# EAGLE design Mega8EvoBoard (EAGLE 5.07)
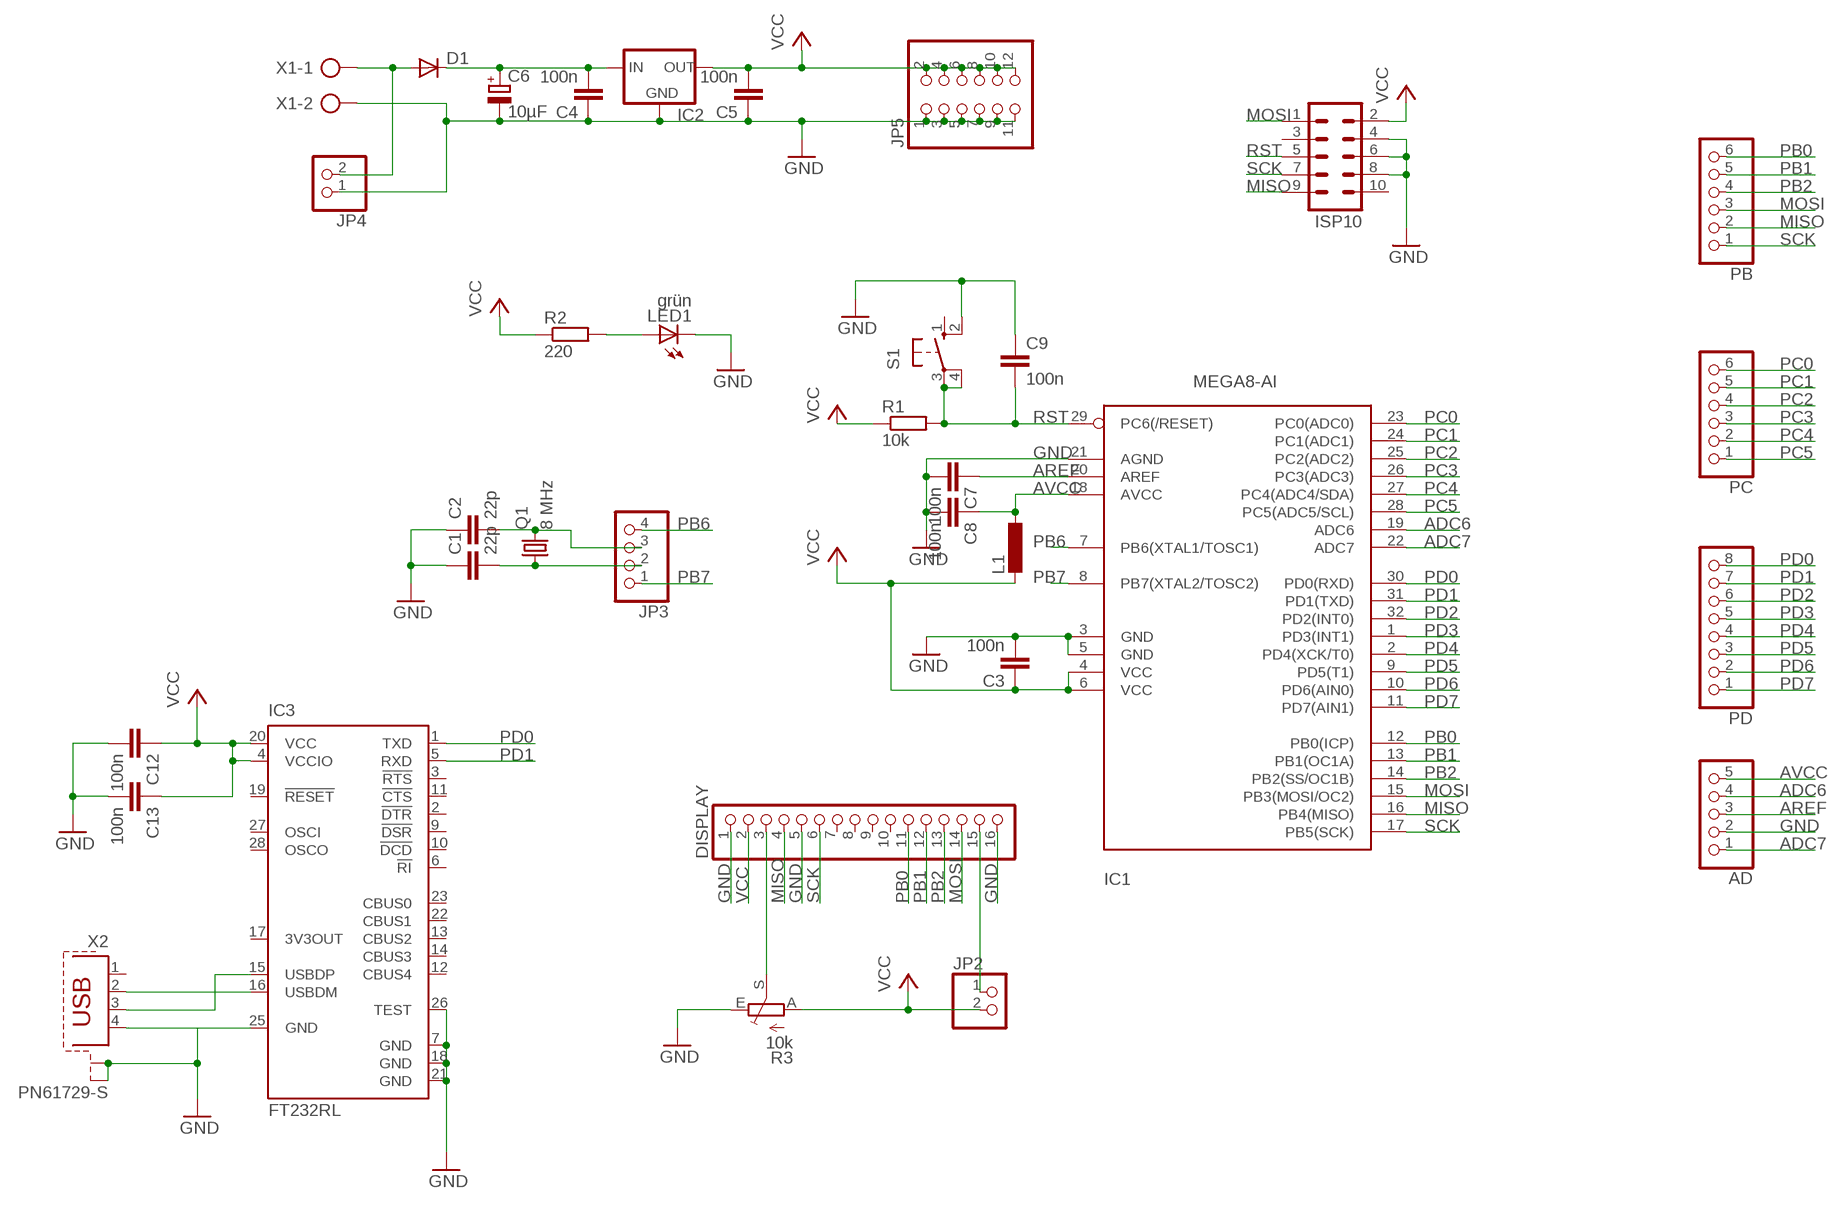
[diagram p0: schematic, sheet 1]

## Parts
AD  PINHD-1X5  [1X05]
C1  22p  C-EUC0805  [C0805]
C2  22p  C-EUC0805  [C0805]
C3  100n  C-EUC1206  [C1206]
C4  100n  C-EUC1206  [C1206]
C5  100n  C-EUC1206  [C1206]
C6  10µF  CPOL-EUE2.5-6  [E2,5-6]
C7  100n  C-EUC1206  [C1206]
C8  100n  C-EUC1206  [C1206]
C9  100n  C-EUC1206  [C1206]
C12  100n  C-EUC1206  [C1206]
C13  100n  C-EUC1206  [C1206]
D1  DIODE-MINIMELF  [MINIMELF]
DISPLAY  PINHD-1X16  [1X16]
IC1  MEGA8-AI  [TQFP32-08]
IC2  78XXS  [78XXS]
IC3  FT232RL  [SSOP28]
ISP10  ML10  [ML10]
JP2  PINHD-1X2  [1X02]
JP3  PINHD-1X4  [1X04]
JP4  PINHD-1X2  [1X02]
JP5  PINHD-2X6  [2X06]
L1  L-EUL2012C  [L2012C]
LED1  grün  LED3MM  [LED3MM]
PB  PINHD-1X6  [1X06]
PC  PINHD-1X6  [1X06]
PD  PINHD-1X8  [1X08]
Q1  8 MHz  CRYSTALHC49UP  [HC49UP]
R1  10k  R-EU_R0805  [R0805]
R2  220  R-EU_R0805  [R0805]
R3  10k  TRIM_EU-PT10  [PT-10]
S1  10-XX  [B3F-10XX]
X1  AK500/2  [AK500/2]
X2  PN61729-S  [PN61729-S]

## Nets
ADC6: AD.4 IC1.19(ADC6)
ADC7: AD.1 IC1.22(ADC7)
AREF: AD.3 C7.1 IC1.20(AREF)
AVCC: AD.5 C8.1 IC1.18(AVCC) L1.1
GND: AD.2 C1.1 C2.1 C3.2 C4.1 C5.1 C6.- C7.2 C8.2 C9.1 C12.2 C13.2 DISPLAY.1 DISPLAY.5 DISPLAY.16 IC1.3(GND) IC1.5(GND) IC1.21(AGND) IC2.GND IC3.7(GND) IC3.18(GND) IC3.21(GND) IC3.25(GND) IC3.26(TEST) ISP10.4 ISP10.6 ISP10.8 JP4.1 JP5.1 JP5.3 JP5.5 JP5.7 JP5.9 JP5.11 LED1.K(C) R3.E S1.2(S1) X1.2 X2.4 X2.S1 X2.S2
MISO: DISPLAY.4 IC1.16(PB4(MISO)) ISP10.9 PB.2
MOSI: DISPLAY.14 IC1.15(PB3(MOSI/OC2)) ISP10.1 PB.3
N$1: D1.A JP4.2 X1.1
N$2: LED1.A R2.2
N$3: C1.2 JP3.2 Q1.1
N$4: DISPLAY.15 JP2.1
N$5: DISPLAY.3 R3.S
N$9: C4.2 C6.+ D1.C IC2.IN
N$12: IC3.16(USBDM) X2.2
N$13: IC3.15(USBDP) X2.3
N$32: C2.2 JP3.3 Q1.2
PB0: DISPLAY.11 IC1.12(PB0(ICP)) PB.6
PB1: DISPLAY.12 IC1.13(PB1(OC1A)) PB.5
PB2: DISPLAY.13 IC1.14(PB2(SS/OC1B)) PB.4
PB6: IC1.7(PB6(XTAL1/TOSC1)) JP3.4
PB7: IC1.8(PB7(XTAL2/TOSC2)) JP3.1
PC0: IC1.23(PC0(ADC0)) PC.6
PC1: IC1.24(PC1(ADC1)) PC.5
PC2: IC1.25(PC2(ADC2)) PC.4
PC3: IC1.26(PC3(ADC3)) PC.3
PC4: IC1.27(PC4(ADC4/SDA)) PC.2
PC5: IC1.28(PC5(ADC5/SCL)) PC.1
PD0: IC1.30(PD0(RXD)) IC3.1(TXD) PD.8
PD1: IC1.31(PD1(TXD)) IC3.5(RXD) PD.7
PD2: IC1.32(PD2(INT0)) PD.6
PD3: IC1.1(PD3(INT1)) PD.5
PD4: IC1.2(PD4(XCK/T0)) PD.4
PD5: IC1.9(PD5(T1)) PD.3
PD6: IC1.10(PD6(AIN0)) PD.2
PD7: IC1.11(PD7(AIN1)) PD.1
RST: C9.2 IC1.29(PC6(/RESET)) ISP10.5 R1.2 S1.3(P) S1.4(P1)
SCK: DISPLAY.6 IC1.17(PB5(SCK)) ISP10.7 PB.1
VCC: C3.1 C5.2 C12.1 C13.1 DISPLAY.2 IC1.4(VCC) IC1.6(VCC) IC2.OUT IC3.4(VCCIO) IC3.20(VCC) ISP10.2 JP2.2 JP5.2 JP5.4 JP5.6 JP5.8 JP5.10 JP5.12 L1.2 R1.1 R2.1 R3.A
Unconnected: DISPLAY.7 DISPLAY.8 DISPLAY.9 DISPLAY.10 IC3.2(!DTR) IC3.3(!RTS) IC3.6(!RI) IC3.9(!DSR) IC3.10(!DCD) IC3.11(!CTS) IC3.12(CBUS4) IC3.13(CBUS2) IC3.14(CBUS3) IC3.17(3V3OUT) IC3.19(!RESET) IC3.22(CBUS1) IC3.23(CBUS0) IC3.27(OSCI) IC3.28(OSCO) ISP10.3 ISP10.10 S1.1(S) X2.1

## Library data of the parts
AD = pinhead:PINHD-1X5: PIN HEADER
C1-C5 C7-C9 C12 C13 = rcl:C-EU: CAPACITOR, European symbol
C6 = rcl:CPOL-EU: POLARIZED CAPACITOR, European symbol
D1 = diode:DIODE-: DIODE
DISPLAY = pinhead:PINHD-1X16: PIN HEADER
IC1 = atmel:MEGA8: MICROCONTROLLER 8 Kbytes FLASH 1 kbytes SRAM 512 bytes EEPROM USART 6-channel 10 bit ADC 2-channel 8 bit ADC Source: avr.lbr
IC2 = v-reg:78XXS: VOLTAGE REGULATOR
IC3 = ftdichip:FT232R: Source: http://www.ftdichip.com/Documents/DataSheets/DS_FT232R_v104.pdf
ISP10 = con-harting-ml:ML10: HARTING
JP2 JP4 = pinhead:PINHD-1X2: PIN HEADER
JP3 = pinhead:PINHD-1X4: PIN HEADER
JP5 = pinhead:PINHD-2X6: PIN HEADER
L1 = rcl:L-EU: INDUCTOR, European symbol
LED1 = led:LED: LED
PB PC = pinhead:PINHD-1X6: PIN HEADER
PD = pinhead:PINHD-1X8: PIN HEADER
Q1 = crystal:CRYSTAL: CRYSTAL
R1 R2 = rcl:R-EU_: RESISTOR, European symbol
R3 = pot:TRIM_EU-: POTENTIOMETER
S1 = switch-omron:10-XX: OMRON SWITCH
X1 = con-ptr500:AK500/2: CONNECTOR
X2 = con-berg:PN61729-S: BERG USB connector

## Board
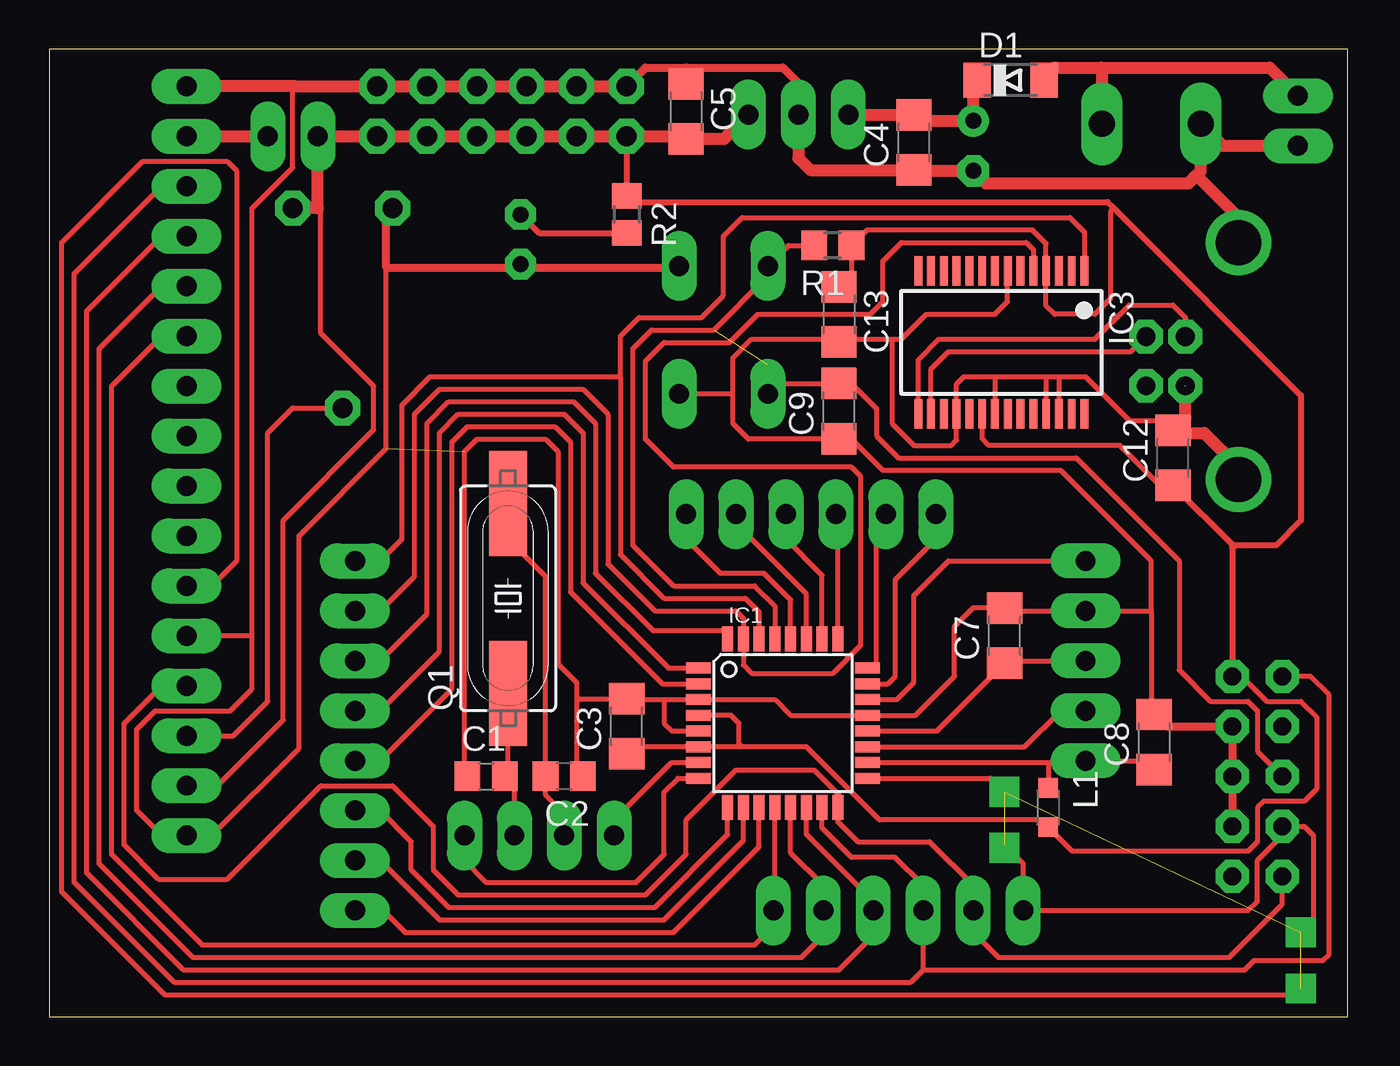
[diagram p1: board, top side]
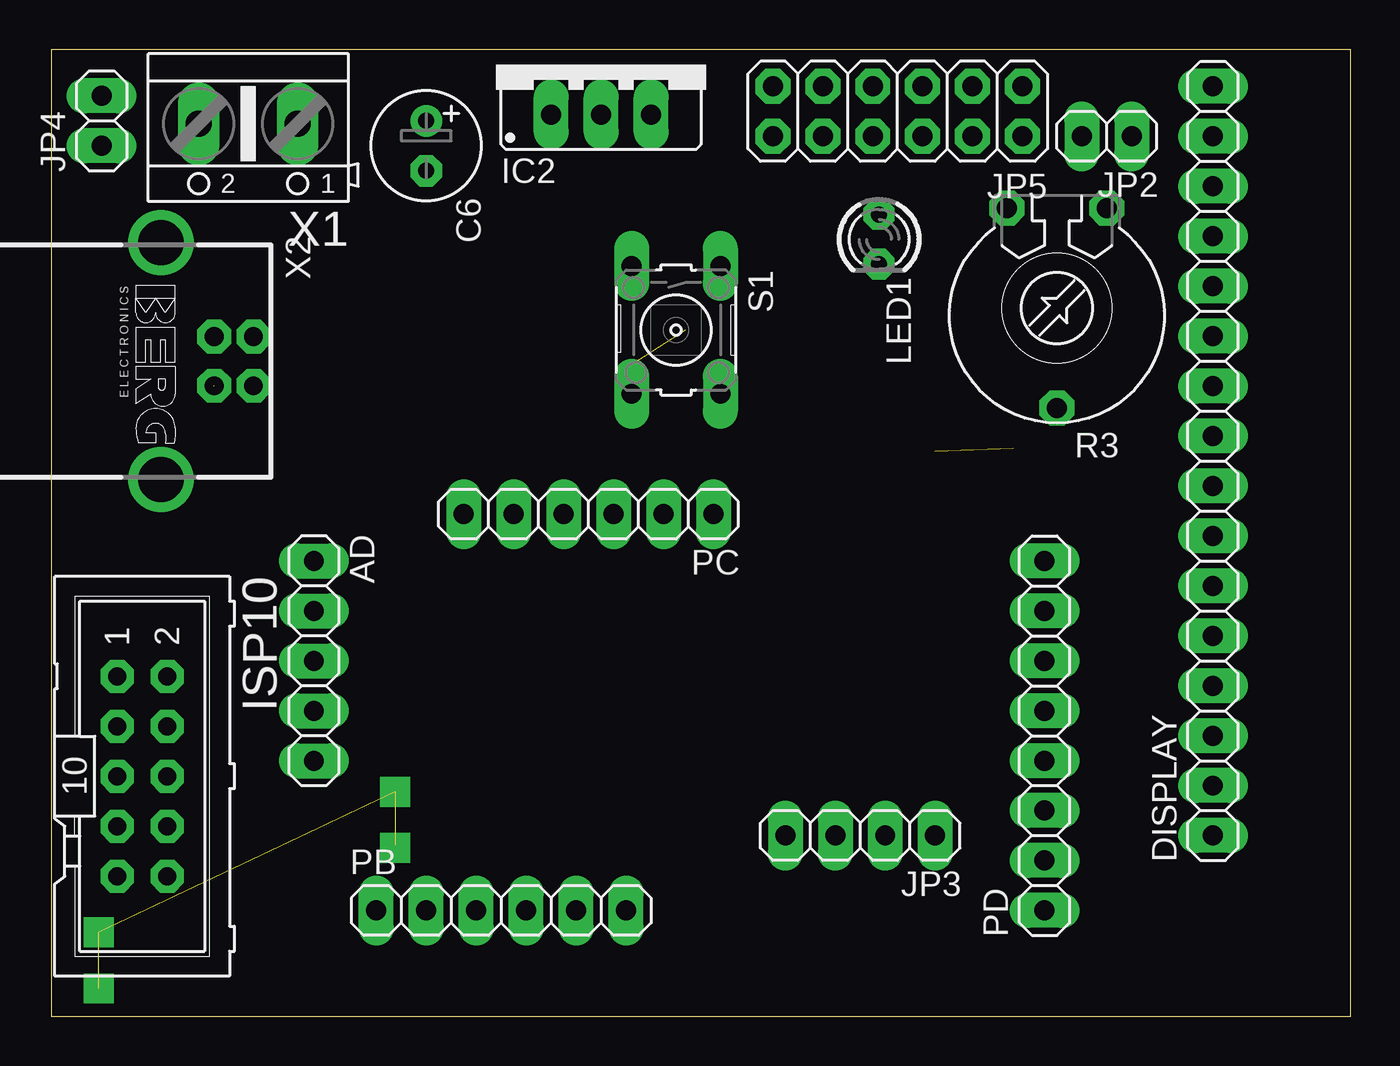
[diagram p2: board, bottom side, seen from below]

Size 66.03 x 49.2 mm. Coordinates in mm from the lower left corner, seen from the top.
Outline: 0,0 66.03,0 66.03,49.2 0,49.2 0,0
Copper layers (1*16): Top 0.035mm / dielectric 1.5mm / Bottom 0.035mm
Design rules "default *": minimum track width 10mil, minimum drill 24mil, track to track 8mil, track to pad 8mil, pad to pad 8mil, via to via 8mil, smd to smd 8mil, copper to edge 40mil, drill to drill 8mil, minimum pad ring 15mil, minimum via ring 8mil, stop-mask expansion 4mil, vias tented up to drill 0mil, thermal gap 10mil

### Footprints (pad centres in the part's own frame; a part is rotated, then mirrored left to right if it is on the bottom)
1X05 = drill 1.016 long: 1 -5.08,0; 2 -2.54,0; 3 0,0; 4 2.54,0; 5 5.08,0
C0805 = smd 1.3 x 1.5: 1 -0.95,0; 2 0.95,0
C1206 = smd 1.6 x 1.8: 1 -1.4,0; 2 1.4,0
E2,5-6 = drill 0.813 pad 1.6 round: + -1.27,0 | drill 0.813 pad 1.6 octagon: - 1.27,0
MINIMELF = smd 1.4 x 1.8: A 1.7,0; C -1.7,0
1X16 = drill 1.016 long: 1 -19.05,0; 2 -16.51,0; 3 -13.97,0; 4 -11.43,0; 5 -8.89,0; 6 -6.35,0; 7 -3.81,0; 8 -1.27,0; 9 1.27,0; 10 3.81,0; 11 6.35,0; 12 8.89,0; 13 11.43,0; 14 13.97,0; 15 16.51,0; 16 19.05,0
TQFP32-08 = smd 1.27 x 0.559: 1 -4.293,2.8; 2 -4.293,2; 3 -4.293,1.2; 4 -4.293,0.4; 5 -4.293,-0.4; 6 -4.293,-1.2; 7 -4.293,-2; 8 -4.293,-2.8; 17 4.293,-2.8; 18 4.293,-2; 19 4.293,-1.2; 20 4.293,-0.4; 21 4.293,0.4; 22 4.293,1.2; 23 4.293,2; 24 4.293,2.8 | smd 0.559 x 1.27: 9 -2.8,-4.293; 10 -2,-4.293; 11 -1.2,-4.293; 12 -0.4,-4.293; 13 0.4,-4.293; 14 1.2,-4.293; 15 2,-4.293; 16 2.8,-4.293; 25 2.8,4.293; 26 2,4.293; 27 1.2,4.293; 28 0.4,4.293; 29 -0.4,4.293; 30 -1.2,4.293; 31 -2,4.293; 32 -2.8,4.293
78XXS = drill 1.016 long: GND 0,-2.54; IN -2.54,-2.54; OUT 2.54,-2.54
SSOP28 = smd 0.4 x 1.5: 1 -4.225,-3.625; 2 -3.575,-3.625; 3 -2.925,-3.625; 4 -2.275,-3.625; 5 -1.625,-3.625; 6 -0.975,-3.625; 7 -0.325,-3.625; 8 0.325,-3.625; 9 0.975,-3.625; 10 1.625,-3.625; 11 2.275,-3.625; 12 2.925,-3.625; 13 3.575,-3.625; 14 4.225,-3.625; 15 4.225,3.625; 16 3.575,3.625; 17 2.925,3.625; 18 2.275,3.625; 19 1.625,3.625; 20 0.975,3.625; 21 0.325,3.625; 22 -0.325,3.625; 23 -0.975,3.625; 24 -1.625,3.625; 25 -2.275,3.625; 26 -2.925,3.625; 27 -3.575,3.625; 28 -4.225,3.625
ML10 = drill 0.914 octagon: 1 -5.08,-1.27; 2 -5.08,1.27; 3 -2.54,-1.27; 4 -2.54,1.27; 5 0,-1.27; 6 0,1.27; 7 2.54,-1.27; 8 2.54,1.27; 9 5.08,-1.27; 10 5.08,1.27
1X02 = drill 1.016 long: 1 -1.27,0; 2 1.27,0
1X04 = drill 1.016 long: 1 -3.81,0; 2 -1.27,0; 3 1.27,0; 4 3.81,0
2X06 = drill 1.016 octagon: 1 -6.35,-1.27; 2 -6.35,1.27; 3 -3.81,-1.27; 4 -3.81,1.27; 5 -1.27,-1.27; 6 -1.27,1.27; 7 1.27,-1.27; 8 1.27,1.27; 9 3.81,-1.27; 10 3.81,1.27; 11 6.35,-1.27; 12 6.35,1.27
L2012C = smd 1 x 1: 1 -1,0; 2 1,0
LED3MM = drill 0.813 octagon: A -1.27,0; K 1.27,0
1X06 = drill 1.016 long: 1 -6.35,0; 2 -3.81,0; 3 -1.27,0; 4 1.27,0; 5 3.81,0; 6 6.35,0
1X08 = drill 1.016 long: 1 -8.89,0; 2 -6.35,0; 3 -3.81,0; 4 -1.27,0; 5 1.27,0; 6 3.81,0; 7 6.35,0; 8 8.89,0
HC49UP = smd 5.334 x 1.93: 1 -4.826,0; 2 4.826,0
R0805 = smd 1.3 x 1.5: 1 -0.95,0; 2 0.95,0
PT-10 = drill 1.016 octagon: A -2.54,-5.08; E 2.54,-5.08; S 0,5.08
B3F-10XX = drill 1.016 long: 1 -3.251,2.261; 2 3.251,2.261; 3 -3.251,-2.261; 4 3.251,-2.261
AK500/2 = drill 1.321 long: 1 -2.515,0; 2 2.515,0
PN61729-S = drill 0.95 octagon: 1 1.25,4.71; 2 -1.25,4.71; 3 -1.25,2.71; 4 1.25,2.71 | drill 2.3 pad 2.9 round: S1 -6.02,0; S2 6.02,0

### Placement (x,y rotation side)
AD  52.7,18.1 270 bottom
C1  22.22,12.22 0 top
C2  26.19,12.22 180 top
C3  29.37,14.76 90 top
C4  43.97,44.45 90 top
C5  32.38,46.04 270 top
C6  46.99,44.29 270 bottom
C7  48.58,19.37 90 top
C8  56.2,13.97 90 top
C9  40.16,30.8 90 top
C12  57.15,28.42 90 top
C13  40.16,35.72 270 top
D1  48.9,47.62 0 top
DISPLAY  6.99,28.26 90 bottom
IC1  37.31,14.92 0 top
IC2  38.1,48.42 0 bottom
IC3  48.42,34.29 180 top
ISP10  61.44,12.22 270 bottom
JP2  12.38,44.77 180 bottom
JP3  24.92,9.21 180 bottom
JP4  63.5,45.56 90 bottom
JP5  23.02,46.04 180 bottom
L1  50.8,10.64 270 top
LED1  23.97,39.53 270 bottom
PB  43.18,5.4 0 bottom
PC  38.73,25.56 180 bottom
PD  15.56,14.29 90 bottom
Q1  23.34,21.27 90 top
R1  39.85,39.21 180 top
R2  29.37,40.8 270 top
R3  14.92,36.04 180 bottom
S1  34.29,34.93 270 bottom
X1  56.04,45.4 180 bottom
X2  60.48,33.34 270 bottom

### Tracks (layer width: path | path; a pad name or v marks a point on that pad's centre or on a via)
ADC6
  Top 0.254: IC1.19 49.6,13.72 51.44,15.56 AD.4
ADC7
  Top 0.254: AD.1 45.72,23.18 43.97,21.43 43.97,16.99 43.11,16.12 IC1.22
AREF
  Top 0.254: IC1.20 45.13,14.52 C7.1 48.71,18.1 AD.3
AVCC
  Top 0.254: IC1.18 50.8,12.92 | 50.8,12.92 52.64,12.92 AD.5 | AD.5 | AD.5 55.75,13.02 C8.1 | L1.1 50.8,12.92
GND  (2 unrouted)
  Top 0.254: 31.27,16.12 IC1.3 36.9,16.12 37.7,15.32 IC1.21 44.06,15.32 46.04,17.3 46.04,19.84 46.99,20.8 48.55,20.8 C7.2 48.71,20.64 AD.2 56.04,20.64 | IC1.5 31.67,14.52 31.27,14.92 31.27,16.12 | 48.09,32.54 46.51,32.54 46.14,32.17 IC3.18 46.14,29.32 45.88,29.05 43.97,29.05 42.86,30.16 42.86,34.45 | 50.69,32.54 51.34,32.54 | 51.34,32.54 IC3.26 | 50.69,32.54 IC3.25 | 48.09,32.54 IC3.21 | 48.09,32.54 50.69,32.54 | 34.77,31.75 34.77,30.16 35.56,29.37 40.16,29.37 | 34.77,31.75 34.77,33.5 35.72,34.45 40.16,34.45 | IC3.7 48.74,36.35 48.1,35.72 44.61,35.72 43.34,34.45 42.86,34.45 | S1.2 34.69,31.67 34.77,31.75 | 31.27,16.12 29.41,16.12 C3.2 26.96,16.16 26.83,16.03 | C2.1 26.83,12.54 26.83,16.03 | 26.83,16.03 26.83,16.99 25.88,17.94 25.88,28.73 25.24,29.37 21.75,29.37 21.11,28.73 21.11,12.38 C1.1 | 10.32,19.37 10.32,16.67 9.21,15.56 5.4,15.56 4.45,14.61 4.45,10.48 5.71,9.21 DISPLAY.1 8.26,9.21 12.7,13.65 12.7,24.45 17.14,28.89 17.14,38.1 | 10.32,19.37 DISPLAY.5 | 10.32,19.37 10.32,41.12 12.38,43.18 12.38,47.31 12.54,47.31 | 40.16,34.45 42.86,34.45 | 23.97,38.1 LED1.K | 56.04,20.64 56.04,15.53 C8.2 | 12.54,47.31 | 40.16,34.45 C13.2 | 40.16,34.45 | 40.16,29.37 C9.1 40.19,29.37 40.8,29.37 42.39,27.78 51.44,27.78 56.04,23.18 56.04,20.64 | 40.16,29.37 | 51.34,32.54 52.7,32.54 54.93,30.32 56.65,30.32 C12.2
  Top 0.406: JP5.11 | JP5.11 30.32,48.26 32.38,48.26 | 32.38,48.26 37.31,48.26 38.1,47.47 IC2.GND | 32.38,48.26 C5.1 | 32.38,48.26 | ISP10.8 ISP10.6 ISP10.4 56.8,14.76 C8.2 | R3.E 17.46,40.96 17.14,40.64 17.14,38.1 23.97,38.1 32.07,38.1
  Top 0.61: X1.2 58.87,45.09 | JP5.1 | JP5.1 JP5.3 JP5.5 JP5.7 JP5.9 JP5.11 | IC2.GND 38.1,43.66 38.71,43.05 C4.1 44,43.02 C6.- 47.62,42.39 57.94,42.39 58.34,42.78 | X1.2 58.55,43 58.34,42.78 | JP5.1 12.54,47.31 DISPLAY.16 | JP4.1 59.66,44.29 X1.2 | X2.S1 60.48,40.64 58.34,42.78 | 57.78,32.08 57.78,30.45 C12.2 57.28,29.69 58.74,29.69 60.48,27.94 X2.S2
MISO
  Top 0.254: DISPLAY.4 5.71,16.83 3.81,14.92 3.81,8.73 5.56,6.99 9.05,6.99 13.81,11.75 17.46,11.75 19.53,9.68 19.53,7.46 20.8,6.19 30.32,6.19 32.38,8.26 32.38,10 34.92,12.54 38.89,12.54 40.16,11.27 40.16,10.69 IC1.16 40.11,9.9 41.12,8.89 44.77,8.89 46.99,6.67 PB.2 | PB.2 | PB.2 | PB.2 46.99,4.29 48.26,3.02 60.01,3.02 62.71,5.71 ISP10.9
MOSI
  Top 0.254: ISP10.1 64.14,17.3 65.09,16.35 65.09,3.17 64.77,2.86 61.28,2.86 60.8,2.38 44.45,2.38 | ISP10.1 | DISPLAY.14 5.71,42.23 1.27,37.78 1.27,6.83 6.35,1.75 43.81,1.75 44.45,2.38 | IC1.15 39.31,9.59 40.8,8.1 43.02,8.1 44.45,6.67 PB.3 | PB.3 | 44.45,2.38 PB.3
N$1
  Top 0.61: D1.A 50.59,47.74 51.12,48.26 53.5,48.26 | X1.1 53.52,48.23 53.5,48.26 | 53.5,48.26 62.07,48.26 JP4.2
N$2
  Top 0.305: R2.2 24.92,39.85 LED1.A
N$3
  Top 0.254: JP3.2 23.65,11.74 C1.2 23.34,12.38 Q1.1
N$4
  Top 0.61: DISPLAY.15 JP2.1
N$5
  Top 0.254: DISPLAY.3 9.37,14.29 11.11,16.03 11.11,29.69 12.38,30.96 R3.S
N$6  (via drill 0 pad 1.52)  (2 unrouted)
  other vias: 48.58,11.43 63.66,4.29 63.66,1.43
N$8  (via drill 0 pad 1.52)
  other vias: 48.58,8.57
N$9
  Top 0.61: D1.C 46.99,47.42 C6.+ 44.26,45.56 C4.2 43.95,45.88 IC2.IN
N$12
  Top 0.254: IC3.16 44.84,32.94 45.72,33.81 55,33.81 X2.2
N$13
  Top 0.254: IC3.15 44.19,33.4 45.24,34.45 53.18,34.45 54.93,36.2 57.15,36.2 57.78,35.56 57.78,34.6 X2.3
N$32
  Top 0.254: JP3.3 26.19,10.32 25.24,11.27 C2.2 25.24,22.38 23.34,24.29 Q1.2 | Q1.2
PB0
  Top 0.254: DISPLAY.11 5.71,34.61 3.17,32.07 3.17,8.26 7.78,3.65 35.88,3.65 36.83,4.6 PB.6 | PB.6 | IC1.12 36.91,5.47 PB.6
PB1
  Top 0.254: DISPLAY.12 5.71,37.15 2.54,33.97 2.54,7.78 7.3,3.02 38.26,3.02 39.37,4.13 PB.5 | PB.5 | IC1.13 37.71,8.33 39.37,6.67 PB.5 | PB.5
PB2
  Top 0.254: DISPLAY.13 5.71,39.69 1.91,35.88 1.91,7.3 6.83,2.38 40.16,2.38 41.91,4.13 PB.4 | PB.4 | IC1.14 38.51,9.28 41.91,5.87 PB.4 | PB.4
PB6
  Top 0.254: IC1.7 31.66,12.92 28.73,10 JP3.4
PB7
  Top 0.254: 32.54,12.06 32.96,12.06 IC1.8 31.97,12.12 31.27,11.43 31.27,8.26 29.84,6.83 22.23,6.83 21.11,7.94 JP3.1 | JP3.1
PC0
  Top 0.254: IC1.23 42.64,16.92 43.02,17.3 43.02,22.23 45.09,24.29 PC.6
PC1
  Top 0.254: IC1.24 41.85,17.72 42.07,17.94 42.07,25.08 PC.5
PC2
  Top 0.254: IC1.25 40.11,25.46 PC.4
PC3
  Top 0.254: IC1.26 39.31,22.45 37.47,24.29 PC.3
PC4
  Top 0.254: IC1.27 38.51,21.5 34.92,25.08 PC.2
PC5
  Top 0.254: IC1.28 37.71,21.19 36.35,22.54 34.13,22.54 32.38,24.29 PC.1
PD0
  Top 0.254: IC1.30 36.11,20.57 35.4,21.27 31.27,21.27 29.05,23.5 29.05,32.54 | IC3.1 52.64,39.91 51.91,40.64 35.24,40.64 34.29,39.69 34.29,36.67 33.18,35.56 30,35.56 29.05,34.61 29.05,32.54 | PD.8 16.83,23.18 17.94,24.29 17.94,31.11 19.37,32.54 29.05,32.54
PD1
  Top 0.254: IC3.5 50.04,39.02 49.69,39.37 43.34,39.37 42.39,38.42 42.39,36.35 41.75,35.72 36.04,35.72 34.61,34.29 31.27,34.29 30.32,33.34 30.32,29.37 31.75,27.94 40.8,27.94 41.27,27.46 41.27,18.89 39.85,17.46 35.72,17.46 35.31,17.88 IC1.31 35.31,20.26 34.92,20.64 30.8,20.64 28.42,23.02 28.42,30.64 27.15,31.91 19.84,31.91 18.57,30.64 18.57,22.38 16.83,20.64 PD.7
PD2
  Top 0.254: IC1.32 34.51,19.63 30.7,19.63 27.78,22.54 27.78,30.16 26.67,31.27 20.32,31.27 19.21,30.16 19.21,20.48 16.83,18.1 PD.6
PD3
  Top 0.254: IC1.1 31.49,17.72 27.15,22.07 27.15,29.69 26.19,30.64 20.8,30.64 19.84,29.69 19.84,18.57 16.83,15.56 PD.5
PD4
  Top 0.254: PD.4 16.83,13.02 20.48,16.67 20.48,29.21 21.27,30 25.72,30 26.51,29.21 26.51,21.59 31.18,16.92 IC1.2
PD5
  Top 0.254: IC1.9 34.51,9.27 30.8,5.56 20.32,5.56 18.41,7.46 18.41,8.89 16.83,10.48 PD.3
PD6
  Top 0.254: IC1.10 35.31,8.95 31.27,4.92 19.84,4.92 16.83,7.94 PD.2
PD7
  Top 0.254: IC1.11 36.11,8.64 31.75,4.29 18.1,4.29 16.99,5.4 PD.1
RST  (1 unrouted)
  Top 0.254: IC1.29 36.91,20.88 35.88,21.91 31.75,21.91 29.69,23.97 29.69,33.97 30.64,34.92 33.81,34.92 36.51,37.62 36.51,38.14 S1.3 37.59,39.21 R1.2 | ISP10.5 | ISP10.5 61.44,13.49 61.44,15.56 60.96,16.03 59.05,16.03 57.47,17.62 57.47,23.18 52.23,28.42 43.18,28.42 42.07,29.53 42.07,30.93 40.8,32.2 C9.2 37.07,32.2 S1.4 36.55,33.14 36.51,33.18
SCK  (2 unrouted)
  Top 0.254: DISPLAY.6 8.26,21.91 9.53,23.18 9.53,43.02 9.05,43.5 4.76,43.5 0.64,39.37 0.64,6.35 5.87,1.11 63.18,1.11 63.66,1.59 | IC1.17 47.88,12.12 48.58,11.43 | 48.58,8.73 49.53,7.78 PB.1 60.96,5.4 61.44,5.87 61.44,7.94 62.71,9.21 ISP10.7 63.82,9.68 64.29,9.21 64.29,4.92 63.66,4.29
VCC
  Top 0.254: C3.1 29.96,13.72 IC1.6 35.24,13.72 | 35.24,13.72 38.51,13.72 42.23,10 51.28,10 51.28,9.95 L1.2 52.02,8.41 60.96,8.41 61.44,8.89 61.44,10.64 61.75,10.95 63.82,10.95 64.45,11.59 64.45,15.24 63.66,16.03 61.91,16.03 60.64,17.3 ISP10.2 | IC1.4 34.68,15.32 35.08,14.92 35.08,13.88 35.24,13.72 | IC3.20 47.44,29.39 47.78,29.05 54.45,29.05 56.36,27.15 57.02,27.15 C12.1 | DISPLAY.2 8.57,11.75 11.91,15.08 11.91,25.24 16.51,29.84 16.51,32.07 13.81,34.77 13.81,40.96 13.65,41.12 | ISP10.2 | C13.1 40.8,37.75 R1.1 41.59,40.01 50.01,40.01 50.69,39.32 IC3.4 50.69,36.14 51.12,35.72 53.18,35.72 53.98,36.51 53.98,40.96 54.13,41.12
  Top 0.305: JP5.12 | JP5.12 R2.1 | R2.1 | R2.1 29.68,41.43 53.82,41.43 54.13,41.12 63.66,31.59 63.66,25.24 62.39,23.97 60.33,23.97 60.17,23.81 | 60.17,23.81 ISP10.2 | 60.17,23.81 60.17,24 C12.1
  Top 0.61: IC2.OUT 34.32,44.64 C5.2 32.26,44.77 JP5.12 JP5.10 JP5.8 JP5.6 JP5.4 JP5.2 JP2.2 13.65,41.12 R3.A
